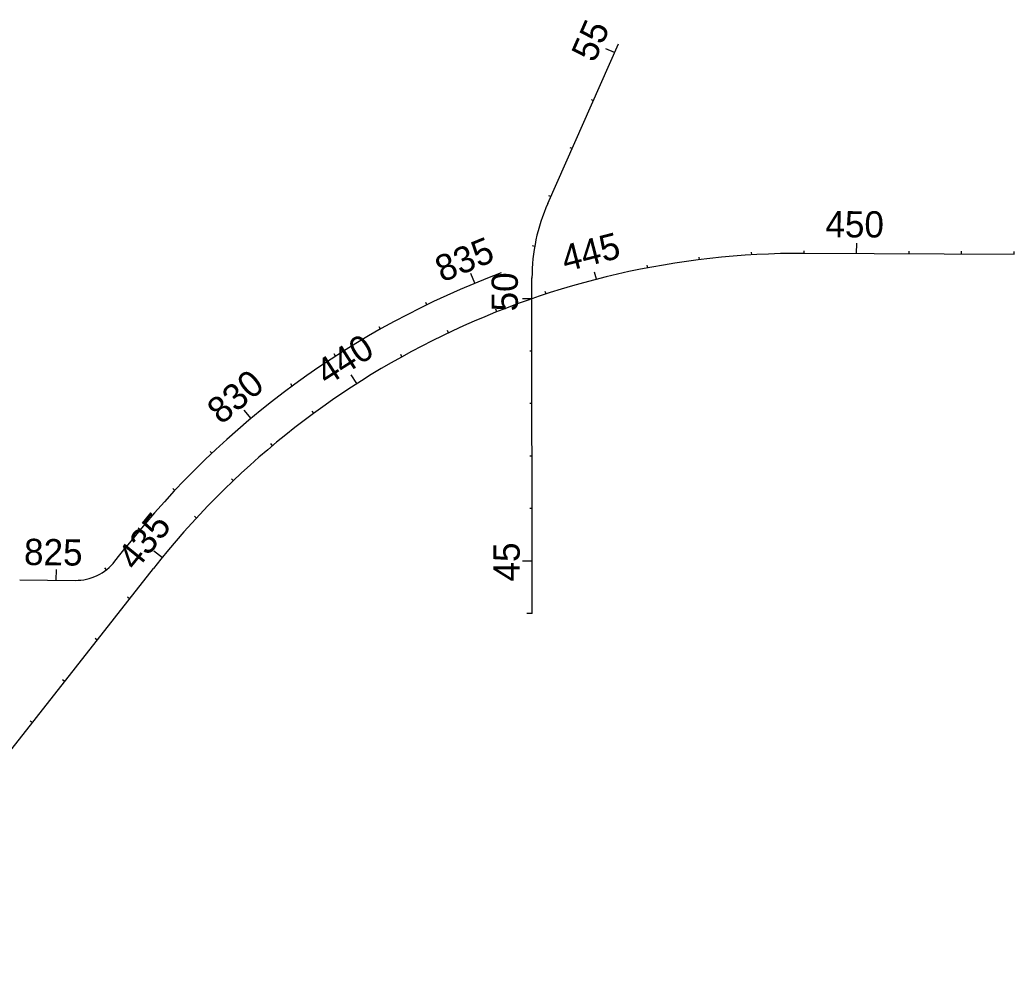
# Model space of a CAD drawing. Extents: x 448091 to 665917, y 1461380 to 1587607.
# Drawn here: x 512901 to 514796, y 1564354 to 1566149 of the extents above; entities that cross this region are included whole.
import ezdxf

# ---------------------------------------------------------------- set-up
doc = ezdxf.new("R2010")
doc.units = 0
doc.layers.add('TextShtNo', color=7, linetype='Continuous')
doc.layers.add('TextTitle', color=7, linetype='Continuous')

msp = doc.modelspace()

# ---------------------------------------------------------------- linework, layer by layer
at = {"layer": 'TextShtNo'}
for p, q in [((513907.2, 1565799.5), (514042, 1566104.1)), ((514396, 1565704.7), (514796, 1565703.4)), ((513877.5, 1565018.3), (513877.2, 1565657.7)), ((513082.5, 1565117.9), (513104.1, 1565145.3)), ((512566.2, 1564354.2), (513155.9, 1565104.5)), ((512901.3, 1565082.9), (513006.5, 1565081.6))]:
    msp.add_line(p, q, dxfattribs=at)
for centre, radius, start, end in [((514227.2, 1565657.8), 350, 156.1178, 180.0231), ((514390.9, 1564133.9), 1570.7, 89.813, 141.8346), ((514390.9, 1564133.9), 1636.7, 110.4621, 141.8346), ((513007.8, 1565176.6), 95, 269.2594, 321.8346)]:
    msp.add_arc(centre, radius, start, end, dxfattribs=at)
at = {"layer": 'TextTitle'}
for p, q in [((514034.5, 1566087.2), (514018.1, 1566094.5)), ((513994, 1565995.7), (513990.4, 1565997.4)), ((513953.6, 1565904.3), (513949.9, 1565905.9)), ((513913.1, 1565812.9), (513909.4, 1565814.5)), ((513882.4, 1565718), (513878.5, 1565718.7)), ((514495.9, 1565704.3), (514496, 1565724.3)), ((514296, 1565701.8), (514295.7, 1565706.8)), ((514395.9, 1565704.7), (514396, 1565709.7)), ((514595.9, 1565704), (514596, 1565709)), ((514695.9, 1565703.7), (514696, 1565708.7)), ((514795.9, 1565703.4), (514796, 1565708.4)), ((514097.7, 1565677.1), (514096.7, 1565682)), ((514196.4, 1565692.6), (514195.8, 1565697.5)), ((513768.2, 1565647.6), (513760.6, 1565666.1)), ((514000.1, 1565655.3), (513996.6, 1565668.8)), ((513904.1, 1565627.3), (513902.5, 1565632.1)), ((513676.9, 1565606.7), (513674.7, 1565611.2)), ((513877.2, 1565618.3), (513859.2, 1565618.3)), ((513810.1, 1565593.3), (513808.2, 1565598)), ((513588.3, 1565560.4), (513585.9, 1565564.7)), ((513718.4, 1565553.4), (513716.2, 1565557.9)), ((513502.7, 1565508.7), (513500, 1565512.9)), ((513629.4, 1565507.8), (513627, 1565512.1)), ((513877.3, 1565518.3), (513873.3, 1565518.3)), ((513543.6, 1565456.5), (513532.8, 1565473.4)), ((513420.4, 1565451.9), (513417.5, 1565455.9)), ((513877.3, 1565418.3), (513873.3, 1565418.3)), ((513341.8, 1565390.2), (513328.9, 1565405.6)), ((513461.2, 1565399.9), (513458.2, 1565404)), ((513382.5, 1565338.2), (513379.3, 1565342.1)), ((513267, 1565323.8), (513263.6, 1565327.4)), ((513877.3, 1565318.3), (513873.3, 1565318.3)), ((513307.9, 1565271.6), (513304.5, 1565275.2)), ((513196.5, 1565253), (513192.8, 1565256.4)), ((513877.4, 1565218.3), (513873.4, 1565218.3)), ((513237.7, 1565200.4), (513234.1, 1565203.8)), ((513130.4, 1565177.9), (513126.5, 1565181.1)), ((513172.2, 1565124.9), (513156.7, 1565137.5)), ((513877.4, 1565118.3), (513859.4, 1565118.3)), ((512970.6, 1565082), (512970.8, 1565102)), ((513066.1, 1565101.6), (513063, 1565105.5)), ((513110.2, 1565046.4), (513106.3, 1565049.5)), ((513877.5, 1565018.3), (513867.5, 1565018.3)), ((513048.5, 1564967.8), (513044.5, 1564970.9)), ((512986.7, 1564889.2), (512982.7, 1564892.2)), ((512924.9, 1564810.5), (512920.9, 1564813.6))]:
    msp.add_line(p, q, dxfattribs=at)

# ---------------------------------------------------------------- texts
for s, rotation, p in [('55', 66.1178, (513996.2, 1566066.3)), ('450', 359.813, (514436.3, 1565735.2)), ('445', 14.4069, (513941, 1565669.3)), ('835', 22.3627, (513706.1, 1565648.8)), ('50', 90.0231, (513850.3, 1565594)), ('440', 32.6456, (513486.4, 1565451.4)), ('830', 39.866, (513284.9, 1565376.9)), ('435', 50.8843, (513121.8, 1565097.7)), ('825', 359.2594, (512908.9, 1565111)), ('45', 90.0231, (513853.8, 1565079.4))]:
    msp.add_text(s, height=50, rotation=rotation, dxfattribs=at).set_placement(p)

doc.saveas('drawing.dxf')
